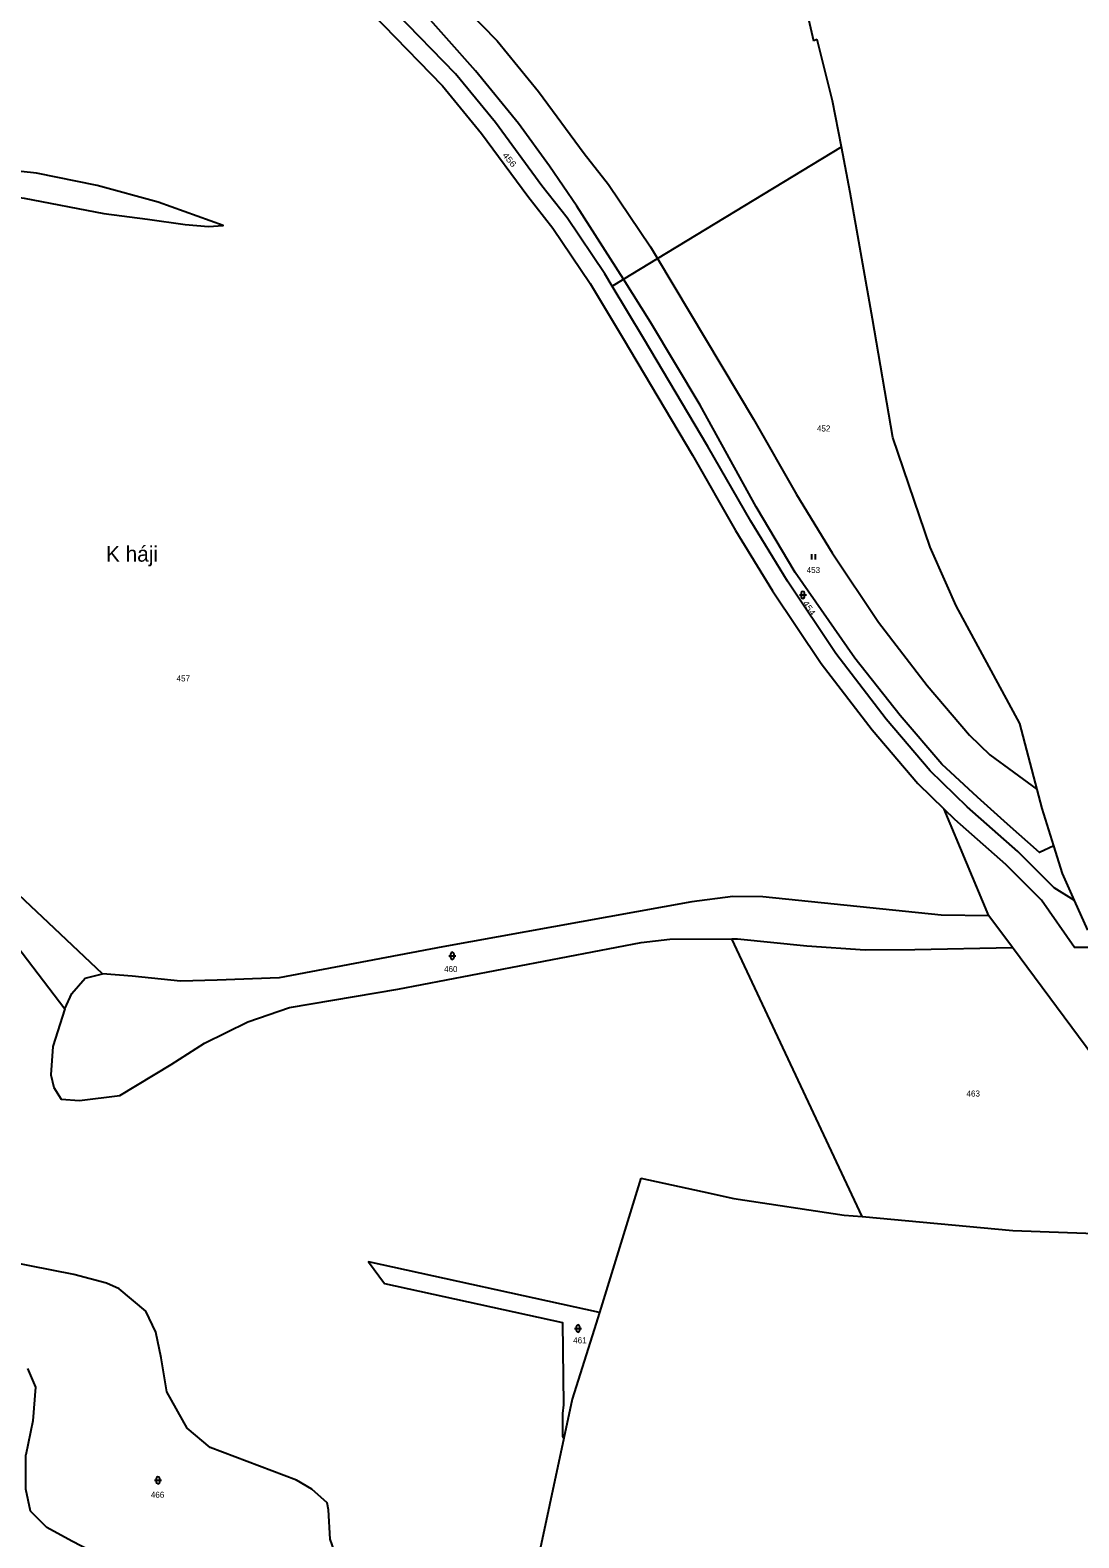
# Model space of a CAD drawing. Extents: x -769392 to -767038, y -1018329 to -1015269.
# Drawn here: x -768027 to -767730.7, y -1016192.3 to -1015766.2 of the extents above; entities that cross this region are included whole.
import ezdxf

# ---------------------------------------------------------------- set-up
doc = ezdxf.new("R2010")
doc.units = 0
doc.header["$LTSCALE"] = 0.68
for name, color, linetype, lineweight in [('1', 7, 'Continuous', 25), ('3', 7, 'Continuous', 25), ('7', 7, 'Continuous', 13)]:
    doc.layers.add(name, color=color, linetype=linetype, lineweight=lineweight)
doc.layers.add('2', color=7, linetype='Continuous')

msp = doc.modelspace()

# ---------------------------------------------------------------- linework, layer by layer
at = {"layer": '1'}
for p, q in [((-767814.33, -1015731.02), (-767805.7, -1015769.26)), ((-767804.66, -1015768.88), (-767805.7, -1015769.26)), ((-767800.33, -1015786.2), (-767804.66, -1015768.88)), ((-767797.8, -1015799.18), (-767800.33, -1015786.2)), ((-767849.73, -1015830.74), (-767797.8, -1015799.18)), ((-767795.27, -1015812.12), (-767797.8, -1015799.18)), ((-767789.01, -1015847.76), (-767795.27, -1015812.12)), ((-767859.4, -1015836.62), (-767849.73, -1015830.74)), ((-767862.53, -1015838.53), (-767859.4, -1015836.62)), ((-767783.24, -1015881.36), (-767789.01, -1015847.76)), ((-767772.7, -1015912.27), (-767783.24, -1015881.36)), ((-767768.3, -1015922.26), (-767772.7, -1015912.27)), ((-767765.37, -1015928.92), (-767768.3, -1015922.26)), ((-767747.4, -1015962.16), (-767765.37, -1015928.92)), ((-767742.47, -1015980.83), (-767747.4, -1015962.16)), ((-767741.07, -1015986.14), (-767742.47, -1015980.83)), ((-767737.79, -1015996.69), (-767741.07, -1015986.14)), ((-767756.11, -1016016.45), (-767768.79, -1015986.33)), ((-767735.33, -1016004.57), (-767737.79, -1015996.69)), ((-767731.9, -1016012.15), (-767735.33, -1016004.57)), ((-767728.12, -1016020.51), (-767731.9, -1016012.15)), ((-767749.41, -1016025.48), (-767756.11, -1016016.45)), ((-767791.95, -1016101.5), (-767828.75, -1016023.02)), ((-767854.43, -1016090.66), (-767866.18, -1016128.56)), ((-767854.43, -1016090.66), (-767837.11, -1016094.37)), ((-767837.11, -1016094.37), (-767828.18, -1016096.36)), ((-767828.18, -1016096.36), (-767797, -1016101.04)), ((-767797, -1016101.04), (-767791.95, -1016101.5)), ((-767791.95, -1016101.5), (-767749.39, -1016105.37)), ((-767749.39, -1016105.37), (-767688.14, -1016107.71)), ((-767866.18, -1016128.56), (-767867.67, -1016133.38)), ((-767867.67, -1016133.38), (-767873.89, -1016153.06)), ((-767873.89, -1016153.06), (-767876.25, -1016164.12)), ((-767876.25, -1016164.12), (-767885.56, -1016207.78))]:
    msp.add_line(p, q, dxfattribs=at)
for points in [[(-768026.23, -1015588.62), (-768021.28, -1015598.42), (-768015.93, -1015607.43), (-768010.09, -1015618.18), (-767990.66, -1015647.78), (-767969.86, -1015677.42), (-767965.65, -1015683.12), (-767954.84, -1015696.33), (-767944.36, -1015710.3), (-767934.37, -1015726.79), (-767925.2, -1015738.37), (-767895.08, -1015769.25), (-767883.4, -1015783.54), (-767870.5, -1015801.03), (-767863.61, -1015809.82), (-767851.68, -1015827.46), (-767849.73, -1015830.74)], [(-767859.4, -1015836.62), (-767872.54, -1015815.98), (-767880.29, -1015804.69), (-767889.07, -1015792.58), (-767901.17, -1015777.71), (-767917.59, -1015759.29), (-767935.31, -1015739.91), (-767943.91, -1015728.27), (-767952.95, -1015714.52), (-767958.16, -1015707.22), (-767971.8, -1015691.16), (-768000.68, -1015645.86), (-768022.75, -1015608.36), (-768026.29, -1015600.63)], [(-767862.53, -1015838.53), (-767864.6, -1015835.09), (-767875.3, -1015819.22), (-767882.4, -1015810.17), (-767895.55, -1015792.34), (-767906.81, -1015778.6), (-767923.66, -1015761.23), (-767936.28, -1015748.55), (-767946.57, -1015735.61), (-767956.21, -1015719.51), (-767966.91, -1015705.24), (-767977.57, -1015692.24), (-767982, -1015686.24), (-768003.03, -1015656.27), (-768028.19, -1015617.91)], [(-768032.78, -1015630.79), (-768026.42, -1015629.72), (-768007.22, -1015659.01), (-767986.09, -1015689.11), (-767981.44, -1015695.41), (-767970.85, -1015708.33), (-767960.37, -1015722.3), (-767950.86, -1015738.18), (-767940.19, -1015751.66), (-767927.2, -1015764.76), (-767910.54, -1015781.93), (-767899.5, -1015795.41), (-767886.42, -1015813.14), (-767879.35, -1015822.16), (-767868.82, -1015837.78), (-767859.46, -1015853.31), (-767839.83, -1015886.35), (-767827.67, -1015907.62), (-767817.21, -1015924.68), (-767803.52, -1015945.16), (-767789.08, -1015963.94), (-767776.19, -1015979.12), (-767768.79, -1015986.33)], [(-768101.13, -1015810.13), (-768094.51, -1015808.91), (-768082.41, -1015808.9), (-768070.71, -1015809.58), (-768058.51, -1015810.25), (-768044.63, -1015811.45), (-768028.69, -1015813.71), (-768006.21, -1015818.03), (-767993.85, -1015819.67), (-767983.23, -1015821.18), (-767976.61, -1015821.7), (-767972.44, -1015821.41), (-767990.87, -1015814.83), (-768008.11, -1015810.14), (-768025.22, -1015806.6), (-768044.3, -1015804.53), (-768095.11, -1015800.38), (-768102.72, -1015799.16)], [(-767849.73, -1015830.74), (-767822.64, -1015876.13), (-767810.46, -1015897.43), (-767800.36, -1015913.89), (-767787.26, -1015933.49), (-767773.52, -1015951.36), (-767761.56, -1015965.45), (-767755.84, -1015971.03), (-767742.47, -1015980.83)], [(-767737.79, -1015996.69), (-767741.82, -1015998.6), (-767750.88, -1015990.62), (-767759.35, -1015982.96), (-767769.36, -1015973.64), (-767781.18, -1015959.87), (-767793.96, -1015943.68), (-767810.87, -1015919.46), (-767821.83, -1015900.92), (-767837.65, -1015872.19), (-767851.7, -1015848.73), (-767859.4, -1015836.62)], [(-767731.9, -1016012.15), (-767737.68, -1016008.55), (-767747.92, -1015998.32), (-767762.25, -1015985.73), (-767772.7, -1015975.54), (-767785.12, -1015960.89), (-767799.36, -1015942.38), (-767813.05, -1015921.9), (-767823.41, -1015905.01), (-767835.49, -1015883.87), (-767853.66, -1015853.26), (-767862.53, -1015838.53)], [(-767725.75, -1016025.41), (-767731.96, -1016025.43), (-767741.21, -1016012.08), (-767751.34, -1016001.97), (-767765.74, -1015989.31), (-767768.79, -1015986.33)], [(-768006.53, -1016032.9), (-768042.22, -1015999.38), (-768052, -1015997.24), (-768017.2, -1016042.76)], [(-767756.11, -1016016.45), (-767769.56, -1016016.31), (-767820.03, -1016011.08), (-767828.49, -1016011.02), (-767840.04, -1016012.58), (-767910.41, -1016025.27), (-767956.68, -1016033.98), (-767974.19, -1016034.63), (-767984.51, -1016034.91), (-767998.17, -1016033.52), (-768006.53, -1016032.9)], [(-768017.2, -1016042.76), (-768020.56, -1016053.46), (-768021.17, -1016061.4), (-768020.31, -1016064.98), (-768018.21, -1016068.26), (-768013.04, -1016068.65), (-768001.64, -1016067.23), (-767987.19, -1016058.46), (-767977.77, -1016052.44), (-767965.54, -1016046.44), (-767953.77, -1016042.42), (-767923.08, -1016037.26), (-767854.34, -1016024), (-767846.26, -1016023.04), (-767828.75, -1016023.02)], [(-767828.75, -1016023.02), (-767827.17, -1016023.02), (-767807.56, -1016024.96), (-767791.08, -1016026.13), (-767777.04, -1016026.05), (-767749.41, -1016025.48)], [(-767684.48, -1016107.71), (-767689.98, -1016102.66), (-767714.03, -1016073.15), (-767749.41, -1016025.48)], [(-768017.2, -1016042.76), (-768015.28, -1016038.4), (-768011.45, -1016034.12), (-768006.53, -1016032.9)], [(-767896.62, -1016240.82), (-767912.56, -1016234.13), (-767920.31, -1016228.66), (-767925.99, -1016221.98), (-767933.3, -1016211.56), (-767939.27, -1016201.17), (-767942.28, -1016192.67), (-767942.7, -1016184.35), (-767943.08, -1016182.35), (-767947.41, -1016178.51), (-767951.73, -1016175.96), (-767976.13, -1016166.75), (-767982.69, -1016161.31), (-767988.39, -1016150.96), (-767989.96, -1016141.37), (-767991.47, -1016134.18), (-767994.3, -1016128.17), (-768001.87, -1016121.89), (-768005.47, -1016120.25), (-768014.65, -1016117.84), (-768027.12, -1016115.35), (-768039.52, -1016112.92), (-768071.74, -1016102.81), (-768088.91, -1016099.25)], [(-767866.18, -1016128.56), (-767931.38, -1016114.27), (-767926.93, -1016120.37), (-767876.6, -1016131.39), (-767876.35, -1016154.63), (-767876.6, -1016157.08), (-767876.6, -1016163.51), (-767876.25, -1016164.12)], [(-768027.74, -1016144.42), (-768025.47, -1016149.67), (-768026.26, -1016159.19), (-768028.24, -1016168.79)], [(-767911.07, -1016254.35), (-767911.35, -1016254.24), (-767913.83, -1016253.23), (-767922.4, -1016249.43), (-767929.72, -1016245.52), (-767936.18, -1016240.92), (-767940.03, -1016237.62), (-767944.46, -1016232.99), (-767951.01, -1016226.59), (-767958.59, -1016221.19), (-767971.23, -1016214.07), (-767985.88, -1016207.38), (-767992.63, -1016204.28), (-768002.1, -1016199.96), (-768015.26, -1016193.2), (-768022.33, -1016189.3), (-768026.9, -1016184.75), (-768028.26, -1016178.48), (-768028.24, -1016168.79)]]:
    msp.add_lwpolyline(points, dxfattribs=at)
at = {"layer": '3'}
for p, q in [((-767806.131, -1015915.79), (-767806.131, -1015914.29)), ((-767805.13, -1015915.79), (-767805.13, -1015914.29)), ((-767809.671, -1015925.801), (-767807.669, -1015925.801)), ((-767809.171, -1015925.301), (-767809.171, -1015926.302)), ((-767808.169, -1015926.302), (-767808.169, -1015925.301)), ((-767908.721, -1016027.801), (-767906.719, -1016027.801)), ((-767908.221, -1016027.301), (-767908.221, -1016028.302)), ((-767907.219, -1016028.302), (-767907.219, -1016027.301)), ((-767873.221, -1016133.101), (-767871.219, -1016133.101)), ((-767872.721, -1016132.601), (-767872.721, -1016133.602)), ((-767871.719, -1016133.602), (-767871.719, -1016132.601)), ((-767991.911, -1016175.981), (-767989.909, -1016175.981)), ((-767991.411, -1016175.481), (-767991.411, -1016176.482)), ((-767990.409, -1016176.482), (-767990.409, -1016175.481))]:
    msp.add_line(p, q, dxfattribs=at)
for centre, start, end in [((-767808.67, -1015925.3009), 0, 180), ((-767808.67, -1015926.3009), 180, 359.98789), ((-767907.72, -1016027.3009), 0, 180), ((-767907.72, -1016028.3009), 180, 359.98789), ((-767872.22, -1016132.6009), 0, 180), ((-767872.22, -1016133.6009), 180, 359.98789), ((-767990.91, -1016175.4809), 0, 180), ((-767990.91, -1016176.4809), 180, 359.98789)]:
    msp.add_arc(centre, 0.5, start, end, dxfattribs=at)

# ---------------------------------------------------------------- texts
at = {"layer": '2'}
for s, rotation, width, p in [('456', 310, 1.2, (-767893.685, -1015801.643)), ('454', 305, 1.15, (-767808.818, -1015928.193))]:
    msp.add_text(s, height=1.7, rotation=rotation, dxfattribs=dict(at, width=width)).set_placement(p)
for s, p in [('452', (-767804.69, -1015879.625)), ('453', (-767807.6, -1015919.625)), ('457', (-767985.64, -1015950.255)), ('460', (-767910.06, -1016032.385)), ('463', (-767762.43, -1016067.555)), ('461', (-767873.57, -1016137.285)), ('466', (-767992.91, -1016180.925))]:
    msp.add_text(s, height=1.7, dxfattribs=at).set_placement(p)
at = {"layer": '7'}
msp.add_text('K háji', height=4.4, dxfattribs=at).set_placement((-768005.6, -1015916.42))

doc.saveas('drawing.dxf')
